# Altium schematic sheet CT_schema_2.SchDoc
size 357 x 214 mm
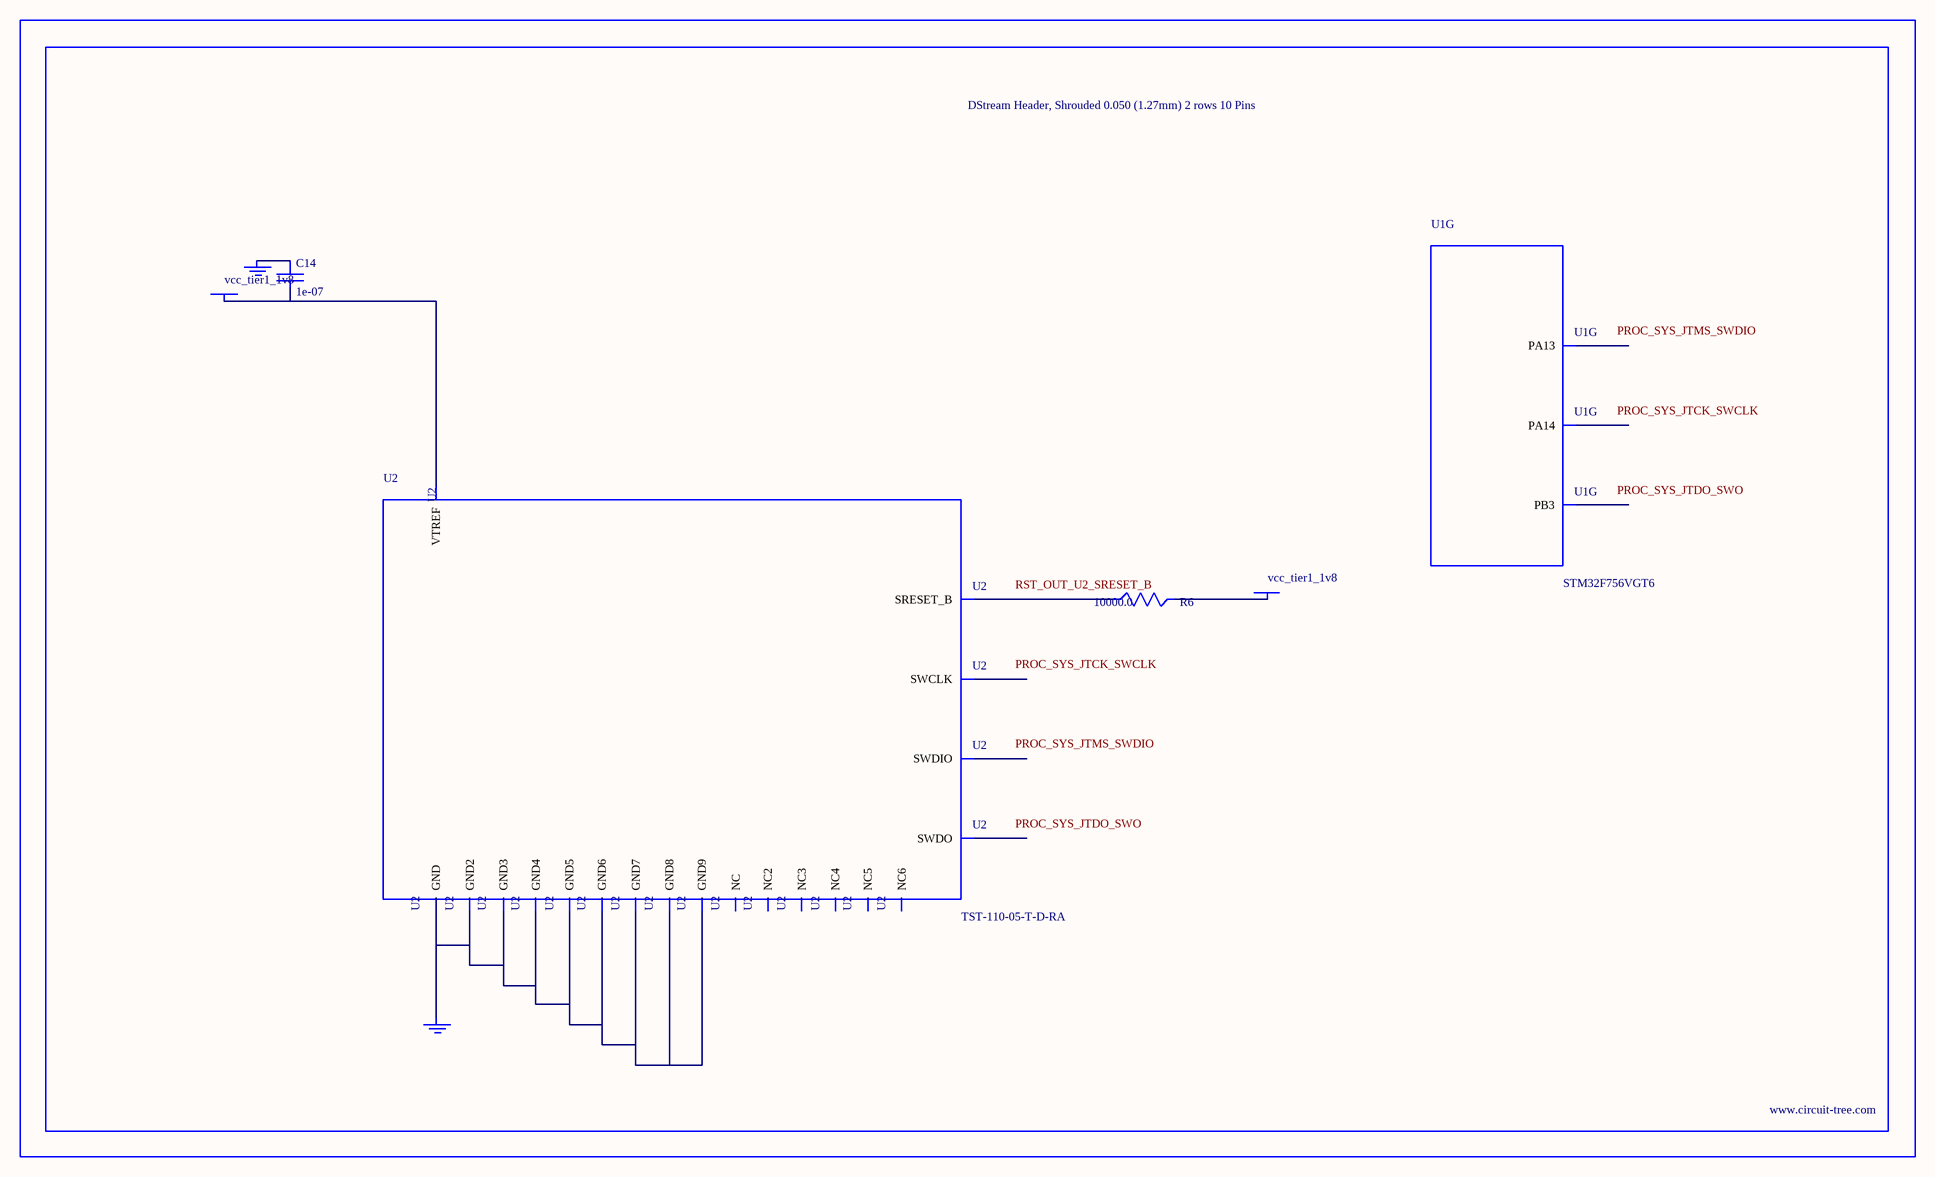
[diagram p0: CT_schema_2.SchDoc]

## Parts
BORDER1  (no value)
C14  1e-07  [C0402]
GND_INSTANCE_1_0  (no value)
GND_INSTANCE_1_1  (no value)
POWER_INSTANCE_1_0  vcc_tier1_1v8
POWER_INSTANCE_1_1  vcc_tier1_1v8
R6  10000.0  [R0603]
U1  STM32F756VGT6  [LQFP100]  (part G of 10)
U2  TST-110-05-T-D-RA  [TST-110-05-T-D-RA]

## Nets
NetC14_1: C14.1 GND_INSTANCE_1_0.0(GND)
NetC14_2: C14.2 POWER_INSTANCE_1_0.0(PWR) U2.1(VTREF)
NetGND_INSTANCE_1_1_0: GND_INSTANCE_1_1.0(GND) U2.4(GND) U2.6(GND2) U2.8(GND3) U2.10(GND4) U2.12(GND5) U2.14(GND6) U2.16(GND7) U2.18(GND8) U2.20(GND9)
NetPOWER_INSTANCE_1_1_0: POWER_INSTANCE_1_1.0(PWR) R6.2
NetR6_1: R6.1 U2.15(SRESET_B)

Not connected (* = marked no-connect by the designer): U1 72(PA13) 76(PA14) 89(PB3); U2 2(NC) 3(NC2) 5(NC3) 7(SWDIO) 9(SWCLK) 11(NC4) 13(SWDO) 17(NC5) 19(NC6)

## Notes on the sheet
- Labels drawn without touching a wire or pin: PROC_SYS_JTCK_SWCLK, PROC_SYS_JTDO_SWO, PROC_SYS_JTMS_SWDIO, RST_OUT_U2_SRESET_B

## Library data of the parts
BORDER1 = BORDER_PAGE1
C14 = C0402C104K3RACTU
GND_INSTANCE_1_0 GND_INSTANCE_1_1 = GND
POWER_INSTANCE_1_0 POWER_INSTANCE_1_1 = PWR
R6 = RC0603JR-0710KL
